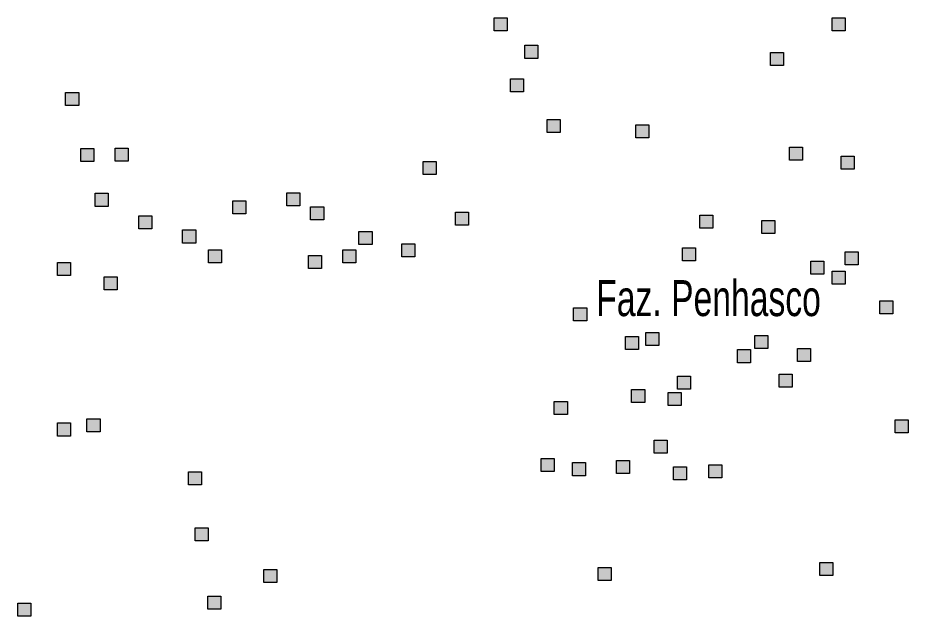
# Model space of a CAD drawing. Extents: x 445.4 to 500, y 8728.7 to 8784.
# Drawn here: x 468.009 to 471.969, y 8731.428 to 8734.089 of the extents above; entities that cross this region are included whole.
import ezdxf

# ---------------------------------------------------------------- set-up
doc = ezdxf.new("R2010")
doc.units = 0
doc.header["$LTSCALE"] = 0.064
doc.layers.add('2', color=7, linetype='Continuous', lineweight=25)
doc.layers.add('61', color=7, linetype='Continuous')

msp = doc.modelspace()

# ---------------------------------------------------------------- hatches: boundary and pattern name
at = {"layer": '2'}
for points in [[(470.1278, 8734.0893), (470.1858, 8734.0893), (470.1858, 8734.0313), (470.1278, 8734.0313)], [(471.6301, 8734.0893), (471.6881, 8734.0893), (471.6881, 8734.0313), (471.6301, 8734.0313)], [(470.2636, 8733.967), (470.3216, 8733.967), (470.3216, 8733.909), (470.2636, 8733.909)], [(471.3563, 8733.9354), (471.4143, 8733.9354), (471.4143, 8733.8774), (471.3563, 8733.8774)], [(470.2002, 8733.8176), (470.2582, 8733.8176), (470.2582, 8733.7596), (470.2002, 8733.7596)], [(468.2214, 8733.7568), (468.2794, 8733.7568), (468.2794, 8733.6988), (468.2214, 8733.6988)], [(470.3631, 8733.6365), (470.4211, 8733.6365), (470.4211, 8733.5785), (470.3631, 8733.5785)], [(470.7568, 8733.6139), (470.8148, 8733.6139), (470.8148, 8733.5559), (470.7568, 8733.5559)], [(468.2893, 8733.5078), (468.3473, 8733.5078), (468.3473, 8733.4498), (468.2893, 8733.4498)], [(468.4415, 8733.5101), (468.4995, 8733.5101), (468.4995, 8733.4521), (468.4415, 8733.4521)], [(471.4401, 8733.5143), (471.4981, 8733.5143), (471.4981, 8733.4563), (471.4401, 8733.4563)], [(471.6708, 8733.4736), (471.7288, 8733.4736), (471.7288, 8733.4156), (471.6708, 8733.4156)], [(469.8111, 8733.4509), (469.8691, 8733.4509), (469.8691, 8733.3929), (469.8111, 8733.3929)], [(468.3526, 8733.3086), (468.4106, 8733.3086), (468.4106, 8733.2506), (468.3526, 8733.2506)], [(469.2047, 8733.3106), (469.2627, 8733.3106), (469.2627, 8733.2526), (469.2047, 8733.2526)], [(468.9651, 8733.2758), (469.0231, 8733.2758), (469.0231, 8733.2178), (468.9651, 8733.2178)], [(469.3111, 8733.2486), (469.3691, 8733.2486), (469.3691, 8733.1906), (469.3111, 8733.1906)], [(468.5472, 8733.209), (468.6052, 8733.209), (468.6052, 8733.151), (468.5472, 8733.151)], [(469.9559, 8733.2245), (470.0139, 8733.2245), (470.0139, 8733.1665), (469.9559, 8733.1665)], [(471.0419, 8733.211), (471.0999, 8733.211), (471.0999, 8733.153), (471.0419, 8733.153)], [(471.3179, 8733.1883), (471.3759, 8733.1883), (471.3759, 8733.1303), (471.3179, 8733.1303)], [(468.7418, 8733.1456), (468.7998, 8733.1456), (468.7998, 8733.0876), (468.7418, 8733.0876)], [(469.526, 8733.1385), (469.584, 8733.1385), (469.584, 8733.0805), (469.526, 8733.0805)], [(469.716, 8733.0842), (469.774, 8733.0842), (469.774, 8733.0262), (469.716, 8733.0262)], [(468.8563, 8733.057), (468.9143, 8733.057), (468.9143, 8732.999), (468.8563, 8732.999)], [(469.3012, 8733.0319), (469.3592, 8733.0319), (469.3592, 8732.9739), (469.3012, 8732.9739)], [(469.4536, 8733.057), (469.5116, 8733.057), (469.5116, 8732.999), (469.4536, 8732.999)], [(470.9649, 8733.0661), (471.0229, 8733.0661), (471.0229, 8733.0081), (470.9649, 8733.0081)], [(471.6889, 8733.048), (471.7469, 8733.048), (471.7469, 8732.99), (471.6889, 8732.99)], [(468.1852, 8733.0007), (468.2432, 8733.0007), (468.2432, 8732.9427), (468.1852, 8732.9427)], [(471.5351, 8733.0072), (471.5931, 8733.0072), (471.5931, 8732.9492), (471.5351, 8732.9492)], [(471.6301, 8732.962), (471.6881, 8732.962), (471.6881, 8732.904), (471.6301, 8732.904)], [(468.3933, 8732.9373), (468.4513, 8732.9373), (468.4513, 8732.8793), (468.3933, 8732.8793)], [(471.8428, 8732.8307), (471.9008, 8732.8307), (471.9008, 8732.7727), (471.8428, 8732.7727)], [(470.4808, 8732.799), (470.5388, 8732.799), (470.5388, 8732.741), (470.4808, 8732.741)], [(470.7115, 8732.6722), (470.7695, 8732.6722), (470.7695, 8732.6142), (470.7115, 8732.6142)], [(470.802, 8732.6903), (470.86, 8732.6903), (470.86, 8732.6323), (470.802, 8732.6323)], [(471.2862, 8732.6767), (471.3442, 8732.6767), (471.3442, 8732.6187), (471.2862, 8732.6187)], [(471.2093, 8732.6133), (471.2673, 8732.6133), (471.2673, 8732.5553), (471.2093, 8732.5553)], [(471.4763, 8732.6179), (471.5343, 8732.6179), (471.5343, 8732.5599), (471.4763, 8732.5599)], [(470.9423, 8732.4956), (471.0003, 8732.4956), (471.0003, 8732.4376), (470.9423, 8732.4376)], [(471.3948, 8732.5047), (471.4528, 8732.5047), (471.4528, 8732.4467), (471.3948, 8732.4467)], [(470.7387, 8732.4368), (470.7967, 8732.4368), (470.7967, 8732.3788), (470.7387, 8732.3788)], [(470.9016, 8732.4232), (470.9596, 8732.4232), (470.9596, 8732.3652), (470.9016, 8732.3652)], [(470.3948, 8732.3824), (470.4528, 8732.3824), (470.4528, 8732.3244), (470.3948, 8732.3244)], [(468.1852, 8732.2872), (468.2432, 8732.2872), (468.2432, 8732.2292), (468.1852, 8732.2292)], [(468.3164, 8732.3053), (468.3744, 8732.3053), (468.3744, 8732.2473), (468.3164, 8732.2473)], [(471.9107, 8732.3009), (471.9687, 8732.3009), (471.9687, 8732.2429), (471.9107, 8732.2429)], [(470.8382, 8732.2104), (470.8962, 8732.2104), (470.8962, 8732.1524), (470.8382, 8732.1524)], [(470.336, 8732.1289), (470.394, 8732.1289), (470.394, 8732.0709), (470.336, 8732.0709)], [(470.6708, 8732.1198), (470.7288, 8732.1198), (470.7288, 8732.0618), (470.6708, 8732.0618)], [(470.4762, 8732.1108), (470.5342, 8732.1108), (470.5342, 8732.0528), (470.4762, 8732.0528)], [(470.9242, 8732.0927), (470.9822, 8732.0927), (470.9822, 8732.0347), (470.9242, 8732.0347)], [(471.0826, 8732.1017), (471.1406, 8732.1017), (471.1406, 8732.0437), (471.0826, 8732.0437)], [(468.7675, 8732.0698), (468.8255, 8732.0698), (468.8255, 8732.0118), (468.7675, 8732.0118)], [(468.7978, 8731.8213), (468.8558, 8731.8213), (468.8558, 8731.7633), (468.7978, 8731.7633)], [(470.5894, 8731.6445), (470.6474, 8731.6445), (470.6474, 8731.5865), (470.5894, 8731.5865)], [(471.5758, 8731.6671), (471.6338, 8731.6671), (471.6338, 8731.6091), (471.5758, 8731.6091)], [(469.1024, 8731.6352), (469.1604, 8731.6352), (469.1604, 8731.5772), (469.1024, 8731.5772)], [(468.0087, 8731.4858), (468.0667, 8731.4858), (468.0667, 8731.4278), (468.0087, 8731.4278)], [(468.8535, 8731.5175), (468.9115, 8731.5175), (468.9115, 8731.4595), (468.8535, 8731.4595)]]:
    msp.add_hatch(color=256, dxfattribs=at).paths.add_polyline_path(points)

# ---------------------------------------------------------------- linework, layer by layer
for points in [[(470.1278, 8734.0893), (470.1858, 8734.0893), (470.1858, 8734.0313), (470.1278, 8734.0313)], [(471.6301, 8734.0893), (471.6881, 8734.0893), (471.6881, 8734.0313), (471.6301, 8734.0313)], [(470.2636, 8733.967), (470.3216, 8733.967), (470.3216, 8733.909), (470.2636, 8733.909)], [(471.3563, 8733.9354), (471.4143, 8733.9354), (471.4143, 8733.8774), (471.3563, 8733.8774)], [(470.2002, 8733.8176), (470.2582, 8733.8176), (470.2582, 8733.7596), (470.2002, 8733.7596)], [(468.2214, 8733.7568), (468.2794, 8733.7568), (468.2794, 8733.6988), (468.2214, 8733.6988)], [(470.3631, 8733.6365), (470.4211, 8733.6365), (470.4211, 8733.5785), (470.3631, 8733.5785)], [(470.7568, 8733.6139), (470.8148, 8733.6139), (470.8148, 8733.5559), (470.7568, 8733.5559)], [(468.2893, 8733.5078), (468.3473, 8733.5078), (468.3473, 8733.4498), (468.2893, 8733.4498)], [(468.4415, 8733.5101), (468.4995, 8733.5101), (468.4995, 8733.4521), (468.4415, 8733.4521)], [(471.4401, 8733.5143), (471.4981, 8733.5143), (471.4981, 8733.4563), (471.4401, 8733.4563)], [(471.6708, 8733.4736), (471.7288, 8733.4736), (471.7288, 8733.4156), (471.6708, 8733.4156)], [(469.8111, 8733.4509), (469.8691, 8733.4509), (469.8691, 8733.3929), (469.8111, 8733.3929)], [(468.3526, 8733.3086), (468.4106, 8733.3086), (468.4106, 8733.2506), (468.3526, 8733.2506)], [(469.2047, 8733.3106), (469.2627, 8733.3106), (469.2627, 8733.2526), (469.2047, 8733.2526)], [(468.9651, 8733.2758), (469.0231, 8733.2758), (469.0231, 8733.2178), (468.9651, 8733.2178)], [(469.3111, 8733.2486), (469.3691, 8733.2486), (469.3691, 8733.1906), (469.3111, 8733.1906)], [(468.5472, 8733.209), (468.6052, 8733.209), (468.6052, 8733.151), (468.5472, 8733.151)], [(469.9559, 8733.2245), (470.0139, 8733.2245), (470.0139, 8733.1665), (469.9559, 8733.1665)], [(471.0419, 8733.211), (471.0999, 8733.211), (471.0999, 8733.153), (471.0419, 8733.153)], [(471.3179, 8733.1883), (471.3759, 8733.1883), (471.3759, 8733.1303), (471.3179, 8733.1303)], [(468.7418, 8733.1456), (468.7998, 8733.1456), (468.7998, 8733.0876), (468.7418, 8733.0876)], [(469.526, 8733.1385), (469.584, 8733.1385), (469.584, 8733.0805), (469.526, 8733.0805)], [(469.716, 8733.0842), (469.774, 8733.0842), (469.774, 8733.0262), (469.716, 8733.0262)], [(468.8563, 8733.057), (468.9143, 8733.057), (468.9143, 8732.999), (468.8563, 8732.999)], [(469.3012, 8733.0319), (469.3592, 8733.0319), (469.3592, 8732.9739), (469.3012, 8732.9739)], [(469.4536, 8733.057), (469.5116, 8733.057), (469.5116, 8732.999), (469.4536, 8732.999)], [(470.9649, 8733.0661), (471.0229, 8733.0661), (471.0229, 8733.0081), (470.9649, 8733.0081)], [(471.6889, 8733.048), (471.7469, 8733.048), (471.7469, 8732.99), (471.6889, 8732.99)], [(468.1852, 8733.0007), (468.2432, 8733.0007), (468.2432, 8732.9427), (468.1852, 8732.9427)], [(471.5351, 8733.0072), (471.5931, 8733.0072), (471.5931, 8732.9492), (471.5351, 8732.9492)], [(471.6301, 8732.962), (471.6881, 8732.962), (471.6881, 8732.904), (471.6301, 8732.904)], [(468.3933, 8732.9373), (468.4513, 8732.9373), (468.4513, 8732.8793), (468.3933, 8732.8793)], [(471.8428, 8732.8307), (471.9008, 8732.8307), (471.9008, 8732.7727), (471.8428, 8732.7727)], [(470.4808, 8732.799), (470.5388, 8732.799), (470.5388, 8732.741), (470.4808, 8732.741)], [(470.7115, 8732.6722), (470.7695, 8732.6722), (470.7695, 8732.6142), (470.7115, 8732.6142)], [(470.802, 8732.6903), (470.86, 8732.6903), (470.86, 8732.6323), (470.802, 8732.6323)], [(471.2862, 8732.6767), (471.3442, 8732.6767), (471.3442, 8732.6187), (471.2862, 8732.6187)], [(471.2093, 8732.6133), (471.2673, 8732.6133), (471.2673, 8732.5553), (471.2093, 8732.5553)], [(471.4763, 8732.6179), (471.5343, 8732.6179), (471.5343, 8732.5599), (471.4763, 8732.5599)], [(470.9423, 8732.4956), (471.0003, 8732.4956), (471.0003, 8732.4376), (470.9423, 8732.4376)], [(471.3948, 8732.5047), (471.4528, 8732.5047), (471.4528, 8732.4467), (471.3948, 8732.4467)], [(470.7387, 8732.4368), (470.7967, 8732.4368), (470.7967, 8732.3788), (470.7387, 8732.3788)], [(470.9016, 8732.4232), (470.9596, 8732.4232), (470.9596, 8732.3652), (470.9016, 8732.3652)], [(470.3948, 8732.3824), (470.4528, 8732.3824), (470.4528, 8732.3244), (470.3948, 8732.3244)], [(468.1852, 8732.2872), (468.2432, 8732.2872), (468.2432, 8732.2292), (468.1852, 8732.2292)], [(468.3164, 8732.3053), (468.3744, 8732.3053), (468.3744, 8732.2473), (468.3164, 8732.2473)], [(471.9107, 8732.3009), (471.9687, 8732.3009), (471.9687, 8732.2429), (471.9107, 8732.2429)], [(470.8382, 8732.2104), (470.8962, 8732.2104), (470.8962, 8732.1524), (470.8382, 8732.1524)], [(470.336, 8732.1289), (470.394, 8732.1289), (470.394, 8732.0709), (470.336, 8732.0709)], [(470.6708, 8732.1198), (470.7288, 8732.1198), (470.7288, 8732.0618), (470.6708, 8732.0618)], [(470.4762, 8732.1108), (470.5342, 8732.1108), (470.5342, 8732.0528), (470.4762, 8732.0528)], [(470.9242, 8732.0927), (470.9822, 8732.0927), (470.9822, 8732.0347), (470.9242, 8732.0347)], [(471.0826, 8732.1017), (471.1406, 8732.1017), (471.1406, 8732.0437), (471.0826, 8732.0437)], [(468.7675, 8732.0698), (468.8255, 8732.0698), (468.8255, 8732.0118), (468.7675, 8732.0118)], [(468.7978, 8731.8213), (468.8558, 8731.8213), (468.8558, 8731.7633), (468.7978, 8731.7633)], [(470.5894, 8731.6445), (470.6474, 8731.6445), (470.6474, 8731.5865), (470.5894, 8731.5865)], [(471.5758, 8731.6671), (471.6338, 8731.6671), (471.6338, 8731.6091), (471.5758, 8731.6091)], [(469.1024, 8731.6352), (469.1604, 8731.6352), (469.1604, 8731.5772), (469.1024, 8731.5772)], [(468.0087, 8731.4858), (468.0667, 8731.4858), (468.0667, 8731.4278), (468.0087, 8731.4278)], [(468.8535, 8731.5175), (468.9115, 8731.5175), (468.9115, 8731.4595), (468.8535, 8731.4595)]]:
    msp.add_lwpolyline(points, close=True, dxfattribs=at)

# ---------------------------------------------------------------- texts
at = {"layer": '61', "width": 0.7}
msp.add_text('Faz. Penhasco', height=0.16, dxfattribs=at).set_placement((470.5813, 8732.7626))

doc.saveas('drawing.dxf')
